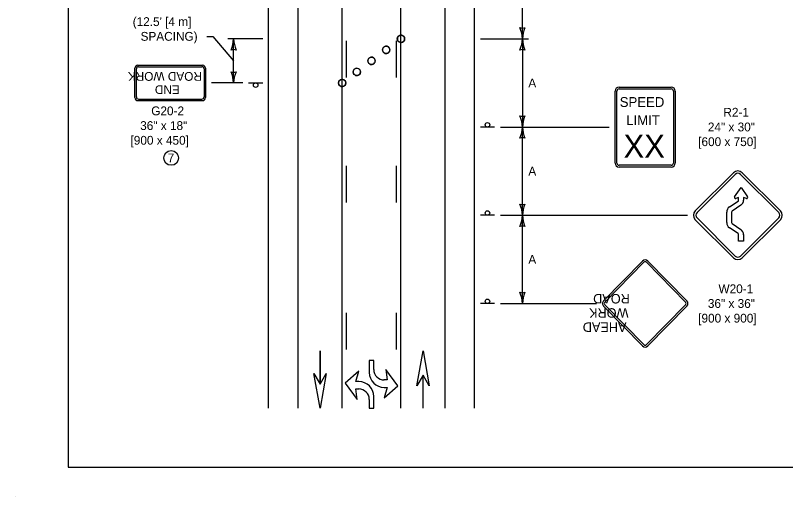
# Model space of a CAD drawing. Extents: x 49991.4 to 50021, y 49987.6 to 50011.4.
# Drawn here: x 49999.98 to 50005.21, y 49999.86 to 50003.14 of the extents above; entities that cross this region are included whole.
import ezdxf

# ---------------------------------------------------------------- set-up
doc = ezdxf.new("R2010")
doc.units = 0
for name, color, linetype in [('Level 1', 7, 'Continuous'), ('Level 2', 7, 'Continuous'), ('Level 3', 7, 'Continuous')]:
    doc.layers.add(name, color=color, linetype=linetype)

msp = doc.modelspace()

# ---------------------------------------------------------------- linework, layer by layer
at = {"layer": 'Level 1'}
for p, q in [((50001.6979, 50000.4631), (50001.6979, 50008.7736)), ((50001.8979, 50000.4631), (50001.8979, 50008.7736)), ((50002.1979, 50000.4631), (50002.1979, 50008.7736)), ((50002.5979, 50000.4631), (50002.5979, 50008.7736)), ((50002.8979, 50000.4631), (50002.8979, 50008.7736)), ((50003.0979, 50000.4631), (50003.0979, 50008.7736)), ((50002.2279, 50002.7131), (50002.2279, 50002.9631)), ((50002.5679, 50002.7131), (50002.5679, 50002.9631)), ((50000.7889, 50002.576), (50000.7889, 50002.776)), ((50000.7989, 50002.581), (50000.7989, 50002.771)), ((50000.809, 50002.796), (50001.249, 50002.796)), ((50000.8139, 50002.786), (50001.2439, 50002.786)), ((50001.2589, 50002.771), (50001.2589, 50002.581)), ((50001.2689, 50002.776), (50001.2689, 50002.576)), ((50001.5619, 50002.676), (50001.6579, 50002.676)), ((50004.0538, 50002.1312), (50004.0538, 50002.6208)), ((50004.0662, 50002.1312), (50004.0662, 50002.6208)), ((50004.081, 50002.6479), (50004.4355, 50002.6479)), ((50004.081, 50002.6355), (50004.4355, 50002.6355)), ((50004.2582, 50002.6461), (50004.2582, 50002.6461)), ((50004.4503, 50002.6208), (50004.4503, 50002.1312)), ((50004.4627, 50002.6208), (50004.4627, 50002.1312)), ((50000.8139, 50002.566), (50001.2439, 50002.566)), ((50000.8089, 50002.556), (50001.2489, 50002.556)), ((50003.2339, 50002.376), (50003.1379, 50002.376)), ((50002.2279, 50001.8631), (50002.2279, 50002.1131)), ((50002.5679, 50001.8631), (50002.5679, 50002.1131)), ((50004.4355, 50002.1164), (50004.081, 50002.1164)), ((50004.4355, 50002.104), (50004.081, 50002.104)), ((50004.8665, 50001.9013), (50004.9106, 50001.9654)), ((50004.9106, 50001.9654), (50004.9547, 50001.9013)), ((50004.8938, 50001.8973), (50004.874, 50001.8911)), ((50004.8938, 50001.8794), (50004.8938, 50001.8973)), ((50004.9471, 50001.8911), (50004.9274, 50001.8973)), ((50004.9274, 50001.8973), (50004.9274, 50001.8794)), ((50004.8313, 50001.8324), (50004.8896, 50001.8715)), ((50004.9083, 50001.8436), (50004.85, 50001.8046)), ((50003.2339, 50001.776), (50003.1379, 50001.776)), ((50004.8123, 50001.7269), (50004.8123, 50001.7967)), ((50004.8458, 50001.7967), (50004.8458, 50001.7268)), ((50004.8897, 50001.6514), (50004.8311, 50001.6912)), ((50004.8499, 50001.719), (50004.9085, 50001.6791)), ((50004.8938, 50001.6005), (50004.8938, 50001.6431)), ((50004.9274, 50001.6441), (50004.9274, 50001.6005)), ((50004.9274, 50001.6005), (50004.8938, 50001.6005)), ((50003.9749, 50001.1942), (50004.2401, 50001.4649)), ((50004.2764, 50001.4649), (50004.5416, 50001.1942)), ((50003.9838, 50001.1855), (50004.2489, 50001.4562)), ((50004.2675, 50001.4562), (50004.5327, 50001.1855)), ((50003.2339, 50001.176), (50003.1379, 50001.176)), ((50004.2401, 50000.8873), (50003.9749, 50001.158)), ((50004.2489, 50000.8959), (50003.9838, 50001.1666)), ((50004.5327, 50001.1666), (50004.2675, 50000.8959)), ((50004.5416, 50001.158), (50004.2764, 50000.8873)), ((50002.2279, 50000.8631), (50002.2279, 50001.1131)), ((50002.5679, 50000.8631), (50002.5679, 50001.1131)), ((50002.0473, 50000.8532), (50002.0473, 50000.6273)), ((50002.0477, 50000.8532), (50002.0477, 50000.6273)), ((50002.4132, 50000.7871), (50002.3825, 50000.7871)), ((50002.3825, 50000.7871), (50002.3825, 50000.7063)), ((50002.4132, 50000.7265), (50002.4132, 50000.7871)), ((50002.3111, 50000.7158), (50002.2192, 50000.635)), ((50002.2907, 50000.6451), (50002.3111, 50000.7158)), ((50002.5765, 50000.6153), (50002.4948, 50000.7265)), ((50002.4948, 50000.7265), (50002.5051, 50000.6557)), ((50002.7479, 50000.4631), (50002.7479, 50000.689)), ((50002.7481, 50000.4631), (50002.7481, 50000.689)), ((50002.2192, 50000.635), (50002.3009, 50000.5238)), ((50002.3111, 50000.6451), (50002.2907, 50000.6451)), ((50002.4786, 50000.6608), (50002.4786, 50000.6608)), ((50002.5051, 50000.6557), (50002.4846, 50000.6557)), ((50002.3009, 50000.5238), (50002.2907, 50000.5945)), ((50002.2907, 50000.5945), (50002.3111, 50000.5945)), ((50002.3171, 50000.5895), (50002.3171, 50000.5895)), ((50002.4846, 50000.5344), (50002.5765, 50000.6153)), ((50002.4846, 50000.6052), (50002.5051, 50000.6052)), ((50002.5051, 50000.6052), (50002.4846, 50000.5344)), ((50002.3825, 50000.5238), (50002.3825, 50000.4631)), ((50002.4132, 50000.4631), (50002.4132, 50000.544)), ((50002.3825, 50000.4631), (50002.4132, 50000.4631)), ((49999.9766, 49999.8624), (49999.9766, 49999.8624))]:
    msp.add_line(p, q, dxfattribs=at)
for points in [[(50008.6146, 50011.2628), (50000.3356, 50011.2628), (50000.3356, 50000.0624), (50008.6146, 50000.0624)], [(50002.7061, 50000.6167), (50002.7479, 50000.8532), (50002.7897, 50000.6167), (50002.7479, 50000.6889)], [(50002.0893, 50000.6996), (50002.0477, 50000.4631), (50002.0057, 50000.6996), (50002.0477, 50000.6274)]]:
    msp.add_lwpolyline(points, close=True, dxfattribs=at)
for points in [[(50004.8581, 50002.0652), (50004.599, 50001.8061)], [(50004.8697, 50002.0536), (50004.6106, 50001.7945)], [(50005.1659, 50001.7945), (50004.9067, 50002.0536)], [(50005.1775, 50001.8061), (50004.9184, 50002.0652)], [(50004.599, 50001.7459), (50004.8581, 50001.4868)], [(50004.6106, 50001.7575), (50004.8697, 50001.4984)], [(50004.9067, 50001.4984), (50005.1659, 50001.7575)], [(50004.9184, 50001.4868), (50005.1775, 50001.7459)]]:
    msp.add_lwpolyline(points, dxfattribs=at)
for centre, radius in [((50002.5979, 50002.976), 0.025), ((50002.4979, 50002.901), 0.025), ((50002.3979, 50002.826), 0.025), ((50002.2979, 50002.751), 0.025), ((50001.6099, 50002.6608), 0.0152), ((50002.1979, 50002.676), 0.025), ((50003.1858, 50002.3911), 0.0152), ((50003.1858, 50001.7911), 0.0152), ((50003.1858, 50001.1911), 0.0152)]:
    msp.add_circle(centre, radius, dxfattribs=at)
for centre, radius, start, end in [((50002.5979, 50002.976), 0.025, 10.3048, 190.3048), ((50002.5979, 50002.976), 0.025, 190.3048, 10.3048), ((50002.4979, 50002.901), 0.025, 10.3048, 190.3048), ((50002.4979, 50002.901), 0.025, 190.3048, 10.3048), ((50002.3979, 50002.826), 0.025, 10.3048, 190.3048), ((50002.3979, 50002.826), 0.025, 190.3048, 10.3048), ((50000.809, 50002.776), 0.02, 90, 180), ((50000.8139, 50002.771), 0.015, 90, 180), ((50001.2439, 50002.771), 0.015, 360, 90), ((50001.249, 50002.776), 0.02, 360, 90), ((50002.2979, 50002.751), 0.025, 10.3048, 190.3048), ((50002.2979, 50002.751), 0.025, 190.3048, 10.3048), ((50002.1979, 50002.676), 0.025, 10.3048, 190.3048), ((50002.1979, 50002.676), 0.025, 190.3048, 10.3048), ((50004.081, 50002.6208), 0.0272, 90, 180), ((50004.081, 50002.6208), 0.0148, 90, 180), ((50004.4355, 50002.6208), 0.0272, 0, 90), ((50004.4355, 50002.6208), 0.0148, 0, 90), ((50000.8089, 50002.576), 0.02, 180, 270), ((50000.8139, 50002.581), 0.015, 180, 270), ((50001.2439, 50002.581), 0.015, 270, 360), ((50001.2489, 50002.576), 0.02, 270, 360), ((50004.081, 50002.1312), 0.0272, 180, 270), ((50004.081, 50002.1312), 0.0148, 180, 270), ((50004.4355, 50002.1312), 0.0148, 270, 360), ((50004.4355, 50002.1312), 0.0272, 270, 360), ((50004.8882, 50002.0351), 0.0426, 45, 135), ((50004.8882, 50002.0351), 0.0262, 45, 135), ((50004.872, 50001.8975), 0.0067, 145.4837, 287.3618), ((50004.8843, 50001.8794), 0.00951, 303.8239, 360), ((50004.8843, 50001.8794), 0.043, 303.8239, 0), ((50004.9491, 50001.8975), 0.0067, 252.6382, 34.5163), ((50004.8553, 50001.7967), 0.043, 123.8239, 180), ((50004.6291, 50001.776), 0.0426, 135, 225), ((50004.6291, 50001.776), 0.0262, 135, 225), ((50004.8553, 50001.7967), 0.00951, 123.8239, 180), ((50005.1474, 50001.776), 0.0262, 315, 45), ((50005.1474, 50001.776), 0.0426, 315, 45), ((50004.8553, 50001.7268), 0.043, 179.9518, 235.7905), ((50004.8553, 50001.7268), 0.00951, 179.9486, 235.7905), ((50004.8843, 50001.6436), 0.043, 0, 55.7905), ((50004.8843, 50001.6436), 0.00951, 357.2362, 55.7905), ((50004.8882, 50001.5169), 0.0426, 225, 315), ((50004.8882, 50001.5169), 0.0262, 225, 315)]:
    msp.add_arc(centre, radius, start, end, dxfattribs=at)
for centre, major_axis, ratio, start_param, end_param in [((50004.2582, 50001.4467), (0, 0.0258), 0.98963, 5.497787, 7.068583), ((50004.2582, 50001.4467), (0, 0.0134), 0.98, 5.497787, 7.068583), ((50003.9929, 50001.176), (0, 0.0258), 0.98963, 0.785394, 2.356194), ((50003.9929, 50001.176), (0, 0.0134), 0.98, 0.785394, 2.356194), ((50004.5235, 50001.176), (0, 0.0134), 0.98, 3.926991, 5.497787), ((50004.5235, 50001.176), (0, 0.0258), 0.98963, 3.926991, 5.497787), ((50004.2582, 50000.9054), (0, -0.0258), 0.98963, 5.497795, 7.068583), ((50004.2582, 50000.9054), (0, -0.0134), 0.98, 5.497795, 7.068583), ((50002.4846, 50000.7063), (-0.1021, 0), 0.990099, 0, 1.570796), ((50002.4846, 50000.7265), (-0.0715, 0), 0.990099, 0, 1.570796), ((50002.3111, 50000.544), (0.1021, 0), 0.990099, 0, 1.570796), ((50002.3111, 50000.5238), (0.0715, 0), 0.990099, 0, 1.570796)]:
    msp.add_ellipse(centre, major_axis=major_axis, ratio=ratio, start_param=start_param, end_param=end_param, dxfattribs=at)
at = {"layer": 'Level 2'}
msp.add_circle((50001.0356, 50002.166), 0.0501, dxfattribs=at)
at = {"layer": 'Level 3'}
for p, q in [((50003.4239, 50002.976), (50003.4239, 50003.576)), ((50001.6579, 50002.976), (50001.4199, 50002.976)), ((50001.4599, 50002.676), (50001.4599, 50002.976)), ((50003.1379, 50002.976), (50003.4639, 50002.976)), ((50003.4239, 50002.976), (50003.4239, 50002.376)), ((50001.5219, 50002.676), (50001.3089, 50002.676)), ((50003.2739, 50002.376), (50004.0138, 50002.376)), ((50003.4239, 50001.776), (50003.4239, 50002.376)), ((50003.2739, 50001.776), (50004.5465, 50001.776)), ((50003.4239, 50001.176), (50003.4239, 50001.776)), ((50003.2739, 50001.176), (50003.9274, 50001.1759))]:
    msp.add_line(p, q, dxfattribs=at)
msp.add_lwpolyline([(50001.2784, 50002.993), (50001.3184, 50002.993), (50001.4599, 50002.826)], dxfattribs=at)
for centre, radius, start, end in [((50003.4239, 50003.1042), 0.0548, 252.1388, 287.8612), ((50003.1911, 50002.9645), 0.233, 2.8273, 22.0772), ((50003.646, 50002.9668), 0.2223, 157.456, 177.6395), ((50001.2377, 50002.9852), 0.2223, 337.456, 357.6395), ((50001.6926, 50002.9875), 0.233, 182.8273, 202.0772), ((50003.2017, 50002.9852), 0.2223, 337.456, 357.6395), ((50003.6566, 50002.9875), 0.233, 182.8273, 202.0772), ((50001.4599, 50002.8478), 0.0548, 72.1388, 107.8612), ((50003.4239, 50002.8478), 0.0548, 72.1388, 107.8612), ((50001.4599, 50002.8042), 0.0548, 252.1388, 287.8612), ((50001.2271, 50002.6645), 0.233, 2.8273, 22.0772), ((50001.682, 50002.6668), 0.2223, 157.456, 177.6395), ((50003.4239, 50002.5042), 0.0548, 252.1388, 287.8612), ((50003.1911, 50002.3645), 0.233, 2.8273, 22.0772), ((50003.646, 50002.3668), 0.2223, 157.456, 177.6395), ((50003.2017, 50002.3852), 0.2223, 337.456, 357.6395), ((50003.6566, 50002.3875), 0.233, 182.8273, 202.0772), ((50003.4239, 50002.2478), 0.0548, 72.1388, 107.8612), ((50003.4239, 50001.9042), 0.0548, 252.1388, 287.8612), ((50003.1911, 50001.7645), 0.233, 2.8273, 22.0772), ((50003.646, 50001.7668), 0.2223, 157.456, 177.6395), ((50003.2017, 50001.7852), 0.2223, 337.456, 357.6395), ((50003.6566, 50001.7875), 0.233, 182.8273, 202.0772), ((50003.4239, 50001.6478), 0.0548, 72.1388, 107.8612), ((50003.4239, 50001.3042), 0.0548, 252.1388, 287.8612), ((50003.1911, 50001.1645), 0.233, 2.8273, 22.0772), ((50003.646, 50001.1668), 0.2223, 157.456, 177.6395)]:
    msp.add_arc(centre, radius, start, end, dxfattribs=at)

# ---------------------------------------------------------------- texts
at = {"layer": 'Level 1'}
for s, height, p in [('ROAD WORK', 0.06, (50001.2447, 50002.7506)), ('END', 0.06, (50001.0941, 50002.6606)), ('ROAD', 0.06453, (50004.154, 50001.2406)), ('WORK', 0.06453, (50004.145, 50001.1438)), ('AHEAD', 0.06453, (50004.1312, 50001.047))]:
    msp.add_text(s, height=height, rotation=180, dxfattribs=at).set_placement(p)
for s, height, p in [('SPEED', 0.06696, (50004.0851, 50002.5128)), ('LIMIT', 0.06696, (50004.1294, 50002.389)), ('XX', 0.15775, (50004.1111, 50002.167))]:
    msp.add_text(s, height=height, dxfattribs=at).set_placement(p)
at = {"layer": 'Level 2'}
for s, p in [("(12.5' [4 m]", (50000.774, 50003.063)), ('SPACING)', (50000.8275, 50002.963)), ('G20-2', (50000.9001, 50002.456)), ('R2-1', (50004.7899, 50002.4465)), ('36" x 18"', (50000.8249, 50002.356)), ('24" x 30"', (50004.6844, 50002.3465)), ('[900 x 450]', (50000.7593, 50002.256)), ('[600 x 750]', (50004.6188, 50002.2465)), ('7', (50001.0118, 50002.136)), ('W20-1', (50004.7567, 50001.246)), ('36" x 36"', (50004.6844, 50001.146)), ('[900 x 900]', (50004.6188, 50001.046))]:
    msp.add_text(s, height=0.06, dxfattribs=at).set_placement(p)
for p in [(50003.4639, 50002.646), (50003.4639, 50002.046), (50003.4639, 50001.446)]:
    msp.add_text('A', height=0.06, rotation=360, dxfattribs=at).set_placement(p)

doc.saveas('drawing.dxf')
